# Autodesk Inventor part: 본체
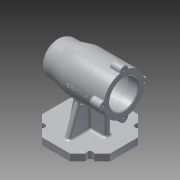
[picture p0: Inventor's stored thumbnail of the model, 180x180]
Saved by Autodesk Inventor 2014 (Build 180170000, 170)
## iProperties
Created: 2021-01
Part Number: 본체
Material: Aluminum 6061
Document SubType Name: Modeling
Designer: kh
Density: 2.71 g/cm^3
Appearance: Aluminum - Flat
Mass: 639.814 g
Surface Area: 618.902 cm^2
Volume: 236.094 cm^3
Author: kh
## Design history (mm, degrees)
sketch "Sketch1"
  geometry: L1 (20.711, 50)-(50, 20.711); L2 (50, 20.711)-(50, -20.711); L3 (50, -20.711)-(20.711, -50); L4 (20.711, -50)-(-20.711, -50); L5 (-20.711, -50)-(-50, -20.711); L6 (-50, -20.711)-(-50, 20.711); L7 (-50, 20.711)-(-20.711, 50); L8 (-20.711, 50)-(20.711, 50); 2 further points
  constraints: 16 end point, 1 coincident, 1 vertical, 17 other
  dimensions: "d0" = 50 distance from line of L2 point (0, 0)
extrude "Extrusion1" new body sketch "Sketch1" distance "d1" = 10; taper "d2" = 0 deg
sketch "Sketch2"
  geometry: L1 (50, 75)-(-50, 75); L2 (-50, 75)-(-50, 105); L3 (-50, 105)-(10, 105); L4 (10, 105)-(30, 100); L5 (30, 100)-(50, 100); L6 (50, 100)-(50, 75); L7 (-50, 0)-(-20.711, 0) reference; L8 (-50, 0)-(-50, 10) reference; L9 (-50, 96)-(-35, 96); L10 (-35, 96)-(-35, 99); L11 (-35, 99)-(7, 99); L12 (7, 99)-(7, 96); L13 (7, 96)-(19, 96); L14 (19, 96)-(19, 92.5); L15 (19, 92.5)-(37, 92.5); L16 (37, 92.5)-(37, 91); L17 (37, 91)-(41, 91); L18 (41, 91)-(41, 85.5); L19 (41, 85.5)-(44, 85.5); L20 (44, 85.5)-(44, 75); 1 further point
  constraints: 36 end point, 9 parallel, 6 perpendicular, 2 collinear, 2 point on line, 1 horizontal
  dimensions: "d3" = 100 distance between parallel lines of L2 L6; "d4" = 75 distance between parallel lines of L7 L1; "d5" = 60 diameter of L3 L1; "d6" = 40 distance from line of L6 L3.end; "d7" = 50 diameter of L5 L1; "d8" = 20 distance of L4.end L5.end; "d9" = 21 diameter of L19 L1; "d10" = 32 diameter of L17 L1; "d11" = 35 diameter of L15 L1; "d12" = 42 diameter of L13 L1; "d13" = 48 diameter of L11 L1; "d14" = 42 diameter of L9 L1; "d15" = 15 distance between parallel lines of L10 L2; "d16" = 42 distance between parallel lines of L10 L12; "d17" = 12 distance between parallel lines of L12 L14; "d18" = 3 distance between parallel lines of L18 L20; "d19" = 4 distance between parallel lines of L16 L18; "d20" = 18 distance between parallel lines of L14 L16
revolve "Revolution1" sketch "Sketch2" stored, may be unused: angle "d21" = 90 deg
sketch "Sketch3"
  geometry: L1 (-27, -4)-(27, -4); L2 (27, -4)-(27, 4); L3 (27, 4)-(-27, 4); L4 (-27, 4)-(-27, -4); L5 (-27, -4)-(27, 4); L6 (27, -4)-(-27, 4); L7 (-50, -20.711)-(-50, 20.711) reference; 1 further point
  constraints: 12 end point, 2 midpoint, 2 parallel, 1 horizontal, 1 perpendicular
  dimensions: "d22" = 8 distance of L1.end L2.end; "d23" = 23 distance between parallel lines of L7 L4
extrude "Extrusion2" join sketch "Sketch3" stored distance "d24" = 10; taper "d25" = 0 deg
feature "FaceDraft1" dims angle "d26" = 11 deg
sketch "Sketch4"
  geometry: L1 (-50, 10)-(-20.711, 10) reference; L2 (-35, 10)-(-20.546, 49.713); 1 further point
  constraints: 2 end point, 1 point on line
  dimensions: "d27" = 110 deg angle of L2 L1; "d28" = 15 distance of L1.start L2.start
feature "Rib1" sketch "Sketch4" dims "d29" = 1, "d30" = 8, "d31" = 0, "d32" = 0, "d33" = 1, "d34" = 1
mirror "Mirror1"
sketch "Sketch5"
  geometry: L1 (0, 0)-(-30, 0); C1 r 6 at (-30, 0); 1 further point
  constraints: 2 end point, 1 centre point, 1 coincident, 1 horizontal, 1 horizontal alignment, 1 other
  dimensions: "d35" = 12 diameter of C1
extrude "Extrusion3" join sketch "Sketch5" distance "d36" = 16; taper "d37" = 0 deg
hole "Hole1" diameter "d40" = 3.242; stored, may be unused: countersink angle "d44" = 90 deg, drill point angle "d46" = 118 deg; dims "d38" = 10, "d39" = 10, "d41" = 8, "d42" = 4, "d43" = 2, "d45" = 10
pattern_circular "Circular Pattern1" dims angle "d48" = 360 deg
sketch "Sketch6"
  geometry: L1 (20.711, -50)-(-20.711, -50) reference; L2 (-20.711, -50)-(-50, -20.711) reference; L3 (-50, -20.711)-(-50, 20.711) reference; L4 (-50, 20.711)-(-20.711, 50) reference; L5 (-20.711, 50)-(20.711, 50) reference; L6 (20.711, 50)-(50, 20.711) reference; L7 (50, 20.711)-(50, -20.711) reference; L8 (50, -20.711)-(20.711, -50) reference; C1 r 4.5 at (-35.355, 35.355); C2 r 4.5 at (-35.355, -35.355); C3 r 4.5 at (35.355, -35.355); C4 r 4.5 at (35.355, 35.355); 1 further point
  constraints: 4 centre point, 1 midpoint, 9 other
  dimensions: "d50" = 9 diameter of C1; "d53" = 360 deg dimension on point (0, 0) C1.centre (derived)
extrude "Extrusion4" cut sketch "Sketch6" stored distance "d55" = 16; taper "d56" = 0 deg
fillet "Fillet1" dims "d57" = 0.3
fillet "Fillet2" dims "d58" = 3
chamfer "Chamfer1" distance "d59" = 1; stored, may be unused: second distance "d60" = 2, angle "d61" = 45 deg
fillet "Fillet3" dims "d62" = 3
fillet "Fillet4" dims "d63" = 3
fillet "Fillet5" dims "d64" = 3
fillet "Fillet6" dims "d65" = 1
workplane "Work Plane2"
  workplane "Work Plane1"
sketch "Sketch8"
  geometry: L1 (-36.949, 10.581)-(20.949, 10.581); L2 (20.949, 10.581)-(20.949, -10.581); L3 (20.949, -10.581)-(-36.949, -10.581); L4 (-36.949, -10.581)-(-36.949, 10.581); L5 (-36.949, 0)-(20.949, 0); L6 (-8, -10.581)-(-8, 10.581); L7 (30, 29.226)-(30, 6.771) reference; L8 (0.711, -75)-(-40.711, -75) reference; 1 further point
  constraints: 4 end point, 4 midpoint, 2 other
  dimensions: "d71" = 38 distance between parallel lines of L7 L6; "d72" = 75 distance between parallel lines of L8 L5
emboss "Emboss2" sketch "Sketch8" dims "d0" = 50, "d73" = 0.5, "d74" = 0
fillet "Fillet7" dims "d75" = 10
body "Solid1"
node "Projected Loop1"
other parameters: "d70" = 0.5
